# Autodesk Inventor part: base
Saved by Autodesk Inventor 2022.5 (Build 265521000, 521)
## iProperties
Created: 2024-12
Part Number: base
Material: Generic
Document SubType Name: Modeling
Designer: AdminForWorker
Density: 1 g/cm^3
Appearance: Default
Title: base
Author: AdminForWorker
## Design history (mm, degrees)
feature "Body2"
body "Solid1"
